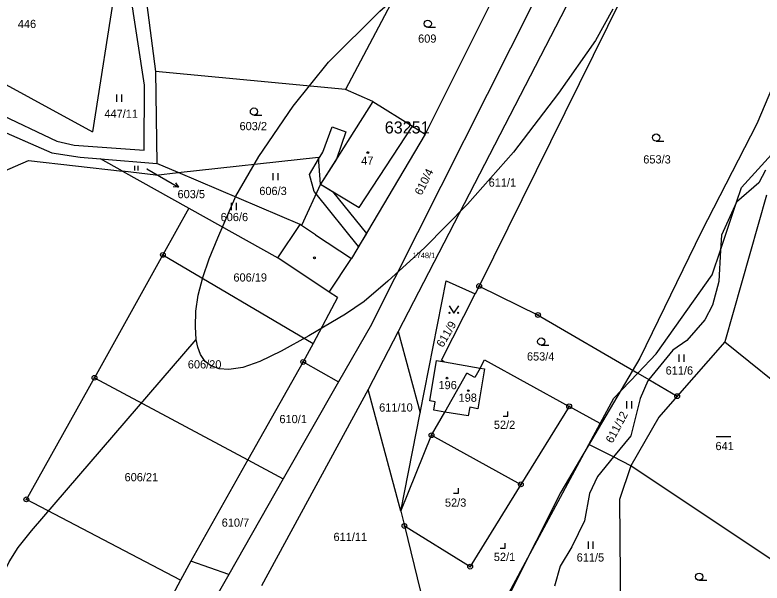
# Model space of a CAD drawing. Extents: x -546762 to -540209, y -1046851 to -1035694.
# Drawn here: x -544335.5 to -544180.8, y -1042661.6 to -1042544 of the extents above; entities that cross this region are included whole.
import ezdxf

# ---------------------------------------------------------------- set-up
doc = ezdxf.new("R2010")
doc.units = 0
for name, color, linetype in [('Vrstva 1', 7, 'Continuous'), ('Vrstva 16', 7, 'Continuous'), ('Vrstva 18', 7, 'Continuous'), ('Vrstva 19', 7, 'Continuous'), ('Vrstva 24', 7, 'Continuous'), ('Vrstva 25', 7, 'Continuous'), ('Vrstva 3', 7, 'Continuous'), ('Vrstva 30', 7, 'Continuous'), ('Vrstva 37', 7, 'Continuous'), ('Vrstva 4', 7, 'Continuous'), ('Vrstva 52', 7, 'Continuous'), ('Vrstva 53', 7, 'Continuous'), ('Vrstva 6', 7, 'Continuous')]:
    doc.layers.add(name, color=color, linetype=linetype)

msp = doc.modelspace()

# ---------------------------------------------------------------- linework, layer by layer
at = {"layer": 'Vrstva 1'}
for p, q in [((-544195.46, -1042492.02), (-544256.13, -1042609.5)), ((-544200.14, -1042520.82), (-544239.35, -1042600.09)), ((-544313.2, -1042576.31), (-544299.46, -1042583.99)), ((-544299.46, -1042583.99), (-544304.85, -1042593.64)), ((-544299.46, -1042583.99), (-544281.07, -1042594.26)), ((-544304.85, -1042593.64), (-544319.03, -1042619.08)), ((-544304.85, -1042593.64), (-544273.74, -1042611.96)), ((-544251.56, -1042626.37), (-544246.16, -1042599.02)), ((-544239.35, -1042600.09), (-544240.16, -1042601.73)), ((-544239.35, -1042600.09), (-544227.17, -1042606.09)), ((-544268.68, -1042602.49), (-544273.74, -1042611.96)), ((-544227.17, -1042606.09), (-544206.52, -1042618.12)), ((-544256.13, -1042609.5), (-544262.34, -1042621.53)), ((-544256.13, -1042609.5), (-544251.56, -1042626.37)), ((-544273.74, -1042611.96), (-544275.79, -1042615.8)), ((-544188.45, -1042611.64), (-544198.34, -1042622.88)), ((-544202.7, -1042614.14), (-544206.52, -1042618.12)), ((-544275.79, -1042615.8), (-544287.24, -1042636.09)), ((-544211.47, -1042623.28), (-544206.52, -1042618.12)), ((-544206.52, -1042618.12), (-544204.19, -1042619.47)), ((-544333.13, -1042644.26), (-544319.03, -1042619.08)), ((-544319.03, -1042619.08), (-544287.24, -1042636.09)), ((-544204.19, -1042619.47), (-544198.34, -1042622.88)), ((-544268.48, -1042619.95), (-544279.93, -1042640.03)), ((-544255.58, -1042646.72), (-544262.34, -1042621.53)), ((-544198.34, -1042622.88), (-544202.14, -1042627.21)), ((-544255.58, -1042646.72), (-544251.56, -1042626.37)), ((-544287.24, -1042636.09), (-544299.06, -1042657.03)), ((-544287.24, -1042636.09), (-544279.93, -1042640.03)), ((-544279.93, -1042640.03), (-544291.18, -1042659.78)), ((-544301.2, -1042660.98), (-544333.13, -1042644.26)), ((-544299.06, -1042657.03), (-544301.2, -1042660.98)), ((-544301.2, -1042660.98), (-544340.32, -1042733.24))]:
    msp.add_line(p, q, dxfattribs=at)
for points in [[(-544249.54, -1042526.36), (-544267.04, -1042559.42)], [(-544231.29, -1042530.03), (-544250.56, -1042568.65)], [(-544261.68, -1042608.03), (-544223.22, -1042531.64)], [(-544308.88, -1042536.45), (-544306.4, -1042555.7)], [(-544314.64, -1042537.74), (-544319.4, -1042568.13)], [(-544308.67, -1042558.52), (-544311.69, -1042538.65)], [(-544357.79, -1042547.23), (-544319.4, -1042568.13)], [(-544306.4, -1042555.7), (-544306.12, -1042574.71)], [(-544267.04, -1042559.42), (-544306.4, -1042555.7)], [(-544308.76, -1042571.95), (-544308.67, -1042558.52)], [(-544261.35, -1042561.91), (-544267.04, -1042559.42)], [(-544261.35, -1042561.91), (-544272.19, -1042578.98)], [(-544261.35, -1042561.91), (-544253.19, -1042567.01)], [(-544185.03, -1042579.7), (-544169.9, -1042563.04)], [(-544339.4, -1042564.19), (-544326.82, -1042570.06)], [(-544253.19, -1042567.01), (-544250.56, -1042568.65)], [(-544339.58, -1042567.41), (-544327.89, -1042572.5)], [(-544250.56, -1042568.65), (-544265.81, -1042594.4)], [(-544326.82, -1042570.06), (-544323.26, -1042570.95)], [(-544323.26, -1042570.95), (-544308.76, -1042571.95)], [(-544327.89, -1042572.5), (-544321.98, -1042573.39)], [(-544321.98, -1042573.39), (-544317.8, -1042573.74)], [(-544317.8, -1042573.74), (-544306.12, -1042574.71)], [(-544313.2, -1042576.31), (-544317.8, -1042573.74)], [(-544301.7, -1042576.59), (-544306.12, -1042574.71)], [(-544301.7, -1042576.59), (-544272.65, -1042573.38)], [(-544272.19, -1042578.98), (-544272.65, -1042573.38)], [(-544306.32, -1042577.1), (-544313.2, -1042576.31)], [(-544306.32, -1042577.1), (-544301.7, -1042576.59)], [(-544276.45, -1042587.33), (-544301.7, -1042576.59)], [(-544272.19, -1042578.98), (-544276.15, -1042587.53)], [(-544186.05, -1042582.74), (-544185.03, -1042579.7)], [(-544179.83, -1042581.29), (-544188.45, -1042611.64)], [(-544189.37, -1042592.68), (-544186.05, -1042582.74)], [(-544281.07, -1042594.26), (-544276.45, -1042587.33)], [(-544276.15, -1042587.53), (-544276.45, -1042587.33)], [(-544191.08, -1042597.8), (-544189.37, -1042592.68)], [(-544270.43, -1042601.33), (-544281.07, -1042594.26)], [(-544270.43, -1042601.33), (-544265.81, -1042594.4)], [(-544202.7, -1042614.14), (-544191.08, -1042597.8)], [(-544246.16, -1042599.02), (-544240.16, -1042601.73)], [(-544268.68, -1042602.49), (-544270.43, -1042601.33)], [(-544247.17, -1042615.47), (-544240.16, -1042601.73)], [(-544261.68, -1042608.03), (-544268.48, -1042619.95)], [(-544188.45, -1042611.64), (-544173.21, -1042623.91)], [(-544275.79, -1042615.8), (-544268.48, -1042619.95)], [(-544249.59, -1042623.84), (-544248.21, -1042615.5)], [(-544248.21, -1042615.5), (-544246.54, -1042615.79)], [(-544246.54, -1042615.79), (-544247.17, -1042615.47)], [(-544246.54, -1042615.79), (-544239.17, -1042617.06)], [(-544239.17, -1042617.06), (-544238.23, -1042615.34)], [(-544238.23, -1042615.34), (-544220.72, -1042625)], [(-544246.48, -1042626.18), (-544241.89, -1042618.15)], [(-544240.23, -1042619), (-544241.89, -1042618.15)], [(-544239.17, -1042617.06), (-544240.23, -1042619)], [(-544238.27, -1042617.21), (-544239.66, -1042625.49)], [(-544239.17, -1042617.06), (-544238.27, -1042617.21)], [(-544262.34, -1042621.53), (-544284.43, -1042662.15)], [(-544248.46, -1042624.04), (-544249.59, -1042623.84)], [(-544248.72, -1042625.8), (-544248.46, -1042624.04)], [(-544214.3, -1042628.55), (-544211.47, -1042623.28)], [(-544246.48, -1042626.18), (-544248.72, -1042625.8)], [(-544241.29, -1042625.2), (-544241.61, -1042626.97)], [(-544239.66, -1042625.49), (-544241.29, -1042625.2)], [(-544220.72, -1042625), (-544230.71, -1042641.16)], [(-544214.3, -1042628.55), (-544220.72, -1042625)], [(-544249.22, -1042630.98), (-544246.48, -1042626.18)], [(-544241.61, -1042626.97), (-544246.48, -1042626.18)], [(-544202.14, -1042627.21), (-544207.91, -1042637.28)], [(-544216.63, -1042632.87), (-544214.3, -1042628.55)], [(-544255.58, -1042646.72), (-544249.22, -1042630.98)], [(-544249.22, -1042630.98), (-544230.71, -1042641.16)], [(-544236.12, -1042669.08), (-544216.63, -1042632.87)], [(-544211.51, -1042635.46), (-544216.63, -1042632.87)], [(-544207.91, -1042637.28), (-544211.51, -1042635.46)], [(-544207.91, -1042637.28), (-544210.3, -1042644.28)], [(-544176.39, -1042658.34), (-544207.91, -1042637.28)], [(-544230.71, -1042641.16), (-544241.22, -1042658.18)], [(-544210.3, -1042644.28), (-544210.07, -1042668.09)], [(-544255.58, -1042646.72), (-544254.84, -1042649.76)], [(-544254.84, -1042649.76), (-544241.22, -1042658.18)], [(-544254.84, -1042649.76), (-544250.19, -1042668.73)], [(-544291.18, -1042659.78), (-544299.06, -1042657.03)], [(-544291.18, -1042659.78), (-544303.88, -1042682.05)]]:
    msp.add_lwpolyline(points, dxfattribs=at)
at = {"layer": 'Vrstva 16'}
msp.add_line((-544304.23, -1042578.12), (-544301.64, -1042579.64), dxfattribs=at)
for points in [[(-544308.17, -1042575.81), (-544304.23, -1042578.12)], [(-544302.25, -1042578.7), (-544301.64, -1042579.64), (-544302.76, -1042579.56)]]:
    msp.add_lwpolyline(points, dxfattribs=at)
at = {"layer": 'Vrstva 24'}
for centre, radius in [((-544304.85, -1042593.64), 0.5), ((-544304.85, -1042593.64), 0.1), ((-544239.35, -1042600.09), 0.5), ((-544239.35, -1042600.09), 0.1), ((-544227.17, -1042606.09), 0.5), ((-544227.17, -1042606.09), 0.1), ((-544275.79, -1042615.8), 0.5), ((-544275.79, -1042615.8), 0.1), ((-544319.03, -1042619.08), 0.5), ((-544319.03, -1042619.08), 0.1), ((-544198.34, -1042622.88), 0.5), ((-544198.34, -1042622.88), 0.1), ((-544220.72, -1042625), 0.5), ((-544220.72, -1042625), 0.1), ((-544249.22, -1042630.98), 0.5), ((-544249.22, -1042630.98), 0.1), ((-544230.71, -1042641.16), 0.5), ((-544230.71, -1042641.16), 0.1), ((-544333.13, -1042644.26), 0.5), ((-544333.13, -1042644.26), 0.1), ((-544254.84, -1042649.76), 0.5), ((-544254.84, -1042649.76), 0.1), ((-544241.22, -1042658.18), 0.5), ((-544241.22, -1042658.18), 0.1)]:
    msp.add_circle(centre, radius, dxfattribs=at)
at = {"layer": 'Vrstva 25'}
for p, q in [((-544250, -1042546.52), (-544248.4, -1042546.52)), ((-544314.37, -1042561.95), (-544314.37, -1042560.45)), ((-544313.37, -1042561.95), (-544313.37, -1042560.45)), ((-544285.99, -1042564.72), (-544284.39, -1042564.72)), ((-544202.69, -1042570.1), (-544201.09, -1042570.1)), ((-544310.65, -1042576.19), (-544310.65, -1042575.19)), ((-544309.97, -1042576.19), (-544309.97, -1042575.19)), ((-544282, -1042578.19), (-544282, -1042576.69)), ((-544281, -1042578.19), (-544281, -1042576.69)), ((-544290.62, -1042584.38), (-544290.62, -1042582.88)), ((-544289.62, -1042584.38), (-544289.62, -1042582.88)), ((-544245.58, -1042604.19), (-544244.58, -1042605.69)), ((-544244.58, -1042605.69), (-544243.58, -1042604.19)), ((-544226.5, -1042612.34), (-544224.9, -1042612.34)), ((-544197.92, -1042615.78), (-544197.92, -1042614.28)), ((-544196.92, -1042615.78), (-544196.92, -1042614.28)), ((-544208.74, -1042625.42), (-544208.74, -1042623.92)), ((-544207.74, -1042625.42), (-544207.74, -1042623.92)), ((-544190.25, -1042631.24), (-544187.25, -1042631.24)), ((-544216.74, -1042654.49), (-544216.74, -1042652.99)), ((-544215.74, -1042654.49), (-544215.74, -1042652.99)), ((-544193.78, -1042661.02), (-544192.18, -1042661.02))]:
    msp.add_line(p, q, dxfattribs=at)
for points in [[(-544234.4, -1042627.04), (-544233.4, -1042627.04), (-544233.4, -1042626.04)], [(-544244.65, -1042642.96), (-544243.65, -1042642.96), (-544243.65, -1042641.96)], [(-544234.99, -1042654.34), (-544233.99, -1042654.34), (-544233.99, -1042653.34)]]:
    msp.add_lwpolyline(points, dxfattribs=at)
for centre, radius in [((-544250, -1042545.77), 0.75), ((-544285.99, -1042563.97), 0.75), ((-544202.69, -1042569.35), 0.75), ((-544262.41, -1042572.45), 0.175), ((-544273.46, -1042594.25), 0.175), ((-544245.48, -1042605.64), 0.112), ((-544243.68, -1042605.64), 0.112), ((-544226.5, -1042611.59), 0.75), ((-544246.01, -1042619.15), 0.175), ((-544241.61, -1042621.75), 0.175), ((-544193.78, -1042660.27), 0.75)]:
    msp.add_circle(centre, radius, dxfattribs=at)
at = {"layer": 'Vrstva 3'}
for points in [[(-544261.35, -1042561.91), (-544272.19, -1042578.98)], [(-544261.35, -1042561.91), (-544253.19, -1042567.01)], [(-544264.19, -1042583.86), (-544253.19, -1042567.01)], [(-544272.19, -1042578.98), (-544264.19, -1042583.86)], [(-544249.59, -1042623.84), (-544248.21, -1042615.5)], [(-544248.21, -1042615.5), (-544246.54, -1042615.79)], [(-544246.54, -1042615.79), (-544239.17, -1042617.06)], [(-544238.27, -1042617.21), (-544239.66, -1042625.49)], [(-544239.17, -1042617.06), (-544238.27, -1042617.21)], [(-544248.46, -1042624.04), (-544249.59, -1042623.84)], [(-544248.72, -1042625.8), (-544248.46, -1042624.04)], [(-544246.48, -1042626.18), (-544248.72, -1042625.8)], [(-544241.29, -1042625.2), (-544241.61, -1042626.97)], [(-544239.66, -1042625.49), (-544241.29, -1042625.2)], [(-544241.61, -1042626.97), (-544246.48, -1042626.18)]]:
    msp.add_lwpolyline(points, dxfattribs=at)
at = {"layer": 'Vrstva 30'}
msp.add_lwpolyline([(-544271.75, -1042572.4), (-544269.8, -1042567.1), (-544266.98, -1042568.14), (-544268.89, -1042573.79), (-544272.19, -1042578.98), (-544269.7, -1042580.5), (-544262.72, -1042589.18), (-544264.35, -1042591.93), (-544273.13, -1042581.02), (-544273.54, -1042580.51), (-544274.51, -1042576.99), (-544272.61, -1042573.84), (-544271.75, -1042572.4)], dxfattribs=at)
at = {"layer": 'Vrstva 37'}
for centre in [(-544262.41, -1042572.45), (-544246.01, -1042619.15)]:
    msp.add_circle(centre, 0.175, dxfattribs=at)
at = {"layer": 'Vrstva 4'}
for p, q in [((-544199.25, -1042613.36), (-544204.19, -1042619.47)), ((-544204.19, -1042619.47), (-544204.39, -1042619.72))]:
    msp.add_line(p, q, dxfattribs=at)
for points in [[(-544264.19, -1042583.86), (-544253.19, -1042567.01)], [(-544180.04, -1042576.12), (-544181.44, -1042578.75)], [(-544272.19, -1042578.98), (-544264.19, -1042583.86)], [(-544181.44, -1042578.75), (-544186.05, -1042582.74)], [(-544186.05, -1042582.74), (-544189.2, -1042589.55)], [(-544273.25, -1042589.46), (-544276.15, -1042587.53)], [(-544273.25, -1042589.46), (-544265.81, -1042594.4)], [(-544189.2, -1042589.55), (-544189.37, -1042592.68)], [(-544189.37, -1042592.68), (-544189.72, -1042599.12)], [(-544189.72, -1042599.12), (-544191.04, -1042604.03)], [(-544191.04, -1042604.03), (-544192.64, -1042607.06)], [(-544192.64, -1042607.06), (-544196.38, -1042611.33)], [(-544196.38, -1042611.33), (-544199.25, -1042613.36)], [(-544204.39, -1042619.72), (-544205.99, -1042623.35)], [(-544205.99, -1042623.35), (-544207.94, -1042631.12)], [(-544207.94, -1042631.12), (-544211.51, -1042635.46)], [(-544211.51, -1042635.46), (-544214.87, -1042639.53)], [(-544214.87, -1042639.53), (-544216.51, -1042643.01)], [(-544216.51, -1042643.01), (-544217.51, -1042648.67)], [(-544217.51, -1042648.67), (-544220.14, -1042654.09)], [(-544220.14, -1042654.09), (-544222.57, -1042658.11)], [(-544222.57, -1042658.11), (-544223.73, -1042662.26)]]:
    msp.add_lwpolyline(points, dxfattribs=at)
at = {"layer": 'Vrstva 52'}
for points in [[(-544297.98, -1042611.14), (-544298.12, -1042608.51), (-544298.05, -1042605.26), (-544297.57, -1042602), (-544296.6, -1042598.33), (-544295.28, -1042594.45), (-544293.47, -1042590.09), (-544289.72, -1042581.49), (-544284.99, -1042573.25), (-544277.85, -1042562.83), (-544270.58, -1042553.74), (-544259.92, -1042543.2), (-544251.2, -1042535.56), (-544243.09, -1042529.75), (-544235.34, -1042525.27), (-544230.37, -1042523.13)], [(-544211.69, -1042542.73), (-544215.27, -1042549.22), (-544222.9, -1042560.13), (-544232.22, -1042572.37), (-544241.79, -1042583.15), (-544250.63, -1042592.12), (-544258.28, -1042599.11), (-544263.18, -1042603.27), (-544267.06, -1042605.88), (-544274.61, -1042610.39), (-544280.34, -1042613.59), (-544284.81, -1042615.73), (-544288.29, -1042616.96), (-544291.18, -1042617.35), (-544293.2, -1042617.23), (-544295.01, -1042616.56), (-544296.08, -1042615.69), (-544297.07, -1042614.23), (-544297.62, -1042612.76), (-544297.98, -1042611.14)], [(-544177.88, -1042557.02), (-544181.87, -1042566.47), (-544193.38, -1042588.93), (-544206.09, -1042615.02), (-544222.41, -1042642.79), (-544232.58, -1042662.94), (-544237.3, -1042674.36), (-544238.61, -1042678.52), (-544240.2, -1042684.33), (-544241.1, -1042689.8), (-544241.64, -1042699.21)], [(-544339.23, -1042663.43), (-544338.4, -1042660.73), (-544336.67, -1042657.2), (-544334.8, -1042654.2), (-544332.07, -1042650.79), (-544297.98, -1042611.14)]]:
    msp.add_lwpolyline(points, dxfattribs=at)
at = {"layer": 'Vrstva 6'}
for points in [[(-544338.09, -1042576.43), (-544332.68, -1042574.08)], [(-544332.68, -1042574.08), (-544313.2, -1042576.31)]]:
    msp.add_lwpolyline(points, dxfattribs=at)

# ---------------------------------------------------------------- texts
at = {"layer": 'Vrstva 16'}
msp.add_text('603/5', height=1.7, dxfattribs=at).set_placement((-544301.82, -1042581.9))
at = {"layer": 'Vrstva 18'}
for s, height, p in [('446', 1.7, (-544334.9, -1042546.67)), ('609', 1.7, (-544252, -1042549.7)), ('447/11', 1.7, (-544316.97, -1042565.26)), ('603/2', 1.7, (-544288.98, -1042567.82)), ('653/3', 1.7, (-544205.37, -1042574.71)), ('603/5', 0.1, (-544308.36, -1042575.81)), ('611/1', 1.7, (-544237.39, -1042579.51)), ('606/3', 1.7, (-544284.89, -1042581.25)), ('606/6', 1.7, (-544292.9, -1042586.65)), ('1748/1', 1.14, (-544253.13, -1042594.31)), ('606/19', 1.7, (-544290.25, -1042599.16)), ('653/4', 1.7, (-544229.46, -1042615.51)), ('606/20', 1.7, (-544299.69, -1042617.15)), ('611/6', 1.7, (-544200.74, -1042618.42)), ('611/10', 1.7, (-544260.07, -1042626.08)), ('610/1', 1.7, (-544280.72, -1042628.48)), ('641', 1.7, (-544190.41, -1042634.06)), ('606/21', 1.7, (-544312.79, -1042640.51)), ('610/7', 1.7, (-544292.68, -1042649.92)), ('611/11', 1.7, (-544269.52, -1042652.88)), ('611/5', 1.7, (-544219.16, -1042657.13))]:
    msp.add_text(s, height=height, dxfattribs=at).set_placement(p)
for s, rotation, p in [('610/4', 63.279, (-544251.31, -1042581.44)), ('611/9', 59.8188, (-544246.87, -1042612.93)), ('611/12', 61.7641, (-544211.77, -1042632.77))]:
    msp.add_text(s, height=1.7, rotation=rotation, dxfattribs=at).set_placement(p)
at = {"layer": 'Vrstva 19'}
for s, p in [('47', (-544263.78, -1042574.97)), ('196', (-544247.78, -1042621.44)), ('198', (-544243.62, -1042624.05)), ('52/2', (-544236.31, -1042629.66)), ('52/3', (-544246.44, -1042645.78)), ('52/1', (-544236.32, -1042657.02))]:
    msp.add_text(s, height=1.7, dxfattribs=at).set_placement(p)
at = {"layer": 'Vrstva 53'}
msp.add_text('63251', height=2.5, dxfattribs=at).set_placement((-544258.91, -1042568.5))

doc.saveas('drawing.dxf')
